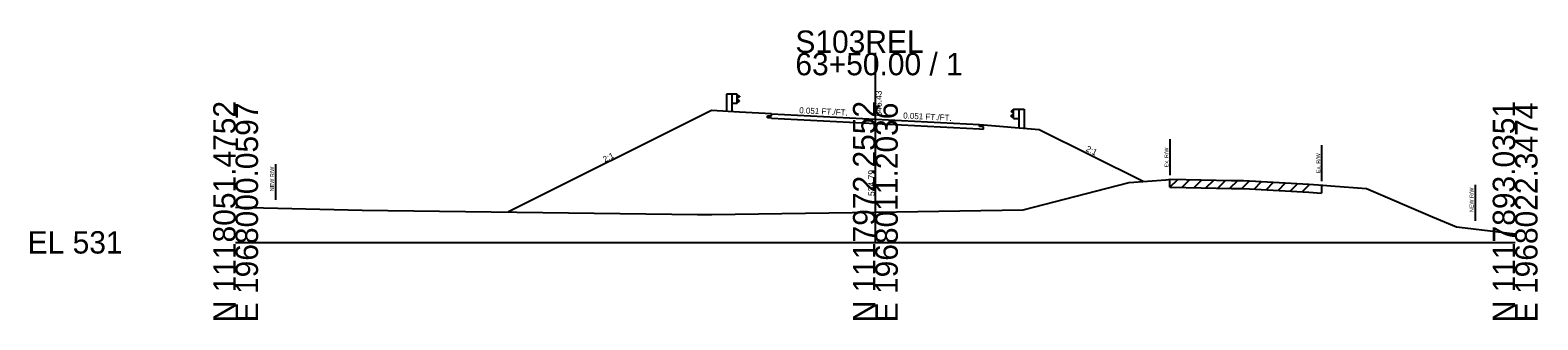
# Model space of a CAD drawing. Extents: x -26 to 163, y -10 to 45020.
# Drawn here: x -25.7 to 162.8, y 21490.3 to 21526.5 of the extents above; entities that cross this region are included whole.
import ezdxf

# ---------------------------------------------------------------- set-up
doc = ezdxf.new("R2010")
doc.units = 0
for name, color, linetype in [('RD_GPK_XS_Cell', 7, 'Continuous'), ('RD_XS_Base', 7, 'Continuous'), ('RD_XS_EarthShd', 7, 'Continuous'), ('RD_XS_ExGround', 7, 'Continuous'), ('RD_XS_ExPaveRet', 7, 'Continuous'), ('RD_XS_ExRW', 7, 'Continuous'), ('RD_XS_GR', 7, 'Continuous'), ('RD_XS_NewRW', 7, 'Continuous'), ('RD_XS_Pave', 7, 'Continuous'), ('RD_XS_PaveOvlay', 7, 'Continuous'), ('RD_XS_TieSlope', 7, 'Continuous'), ('RD_XS_TX_Elev_EX', 7, 'Continuous'), ('RD_XS_TX_Elev_PR', 7, 'Continuous'), ('RD_XS_TX_Slope', 7, 'Continuous')]:
    doc.layers.add(name, color=color, linetype=linetype)

msp = doc.modelspace()

# ---------------------------------------------------------------- linework, layer by layer
at = {"layer": 'RD_GPK_XS_Cell'}
for p, q in [((80, 21500), (80, 21523.7)), ((0, 21500), (80, 21500)), ((80, 21500), (160, 21500))]:
    msp.add_line(p, q, dxfattribs=at)
at = {"layer": 'RD_XS_Base'}
for p, q in [((67, 21515.53), (80, 21514.87)), ((80, 21514.87), (93, 21514.2))]:
    msp.add_line(p, q, dxfattribs=at)
at = {"layer": 'RD_XS_EarthShd'}
for p, q in [((63, 21516.3), (59.5, 21516.48)), ((67, 21516.09), (63, 21516.3)), ((93, 21514.76), (100.5, 21514.13))]:
    msp.add_line(p, q, dxfattribs=at)
at = {"layer": 'RD_XS_ExGround'}
for p, q in [((111.73, 21507.5), (116.33, 21507.84)), ((116.33, 21507.84), (116.96, 21507.9)), ((116.96, 21507.9), (124.54, 21507.75)), ((98.47, 21504.07), (110.26, 21507.11)), ((110.26, 21507.11), (111.73, 21507.5)), ((124.54, 21507.75), (126.03, 21507.74)), ((126.03, 21507.74), (134.19, 21507.26)), ((134.19, 21507.26), (135.94, 21507.17)), ((135.94, 21507.17), (136.95, 21507.08)), ((136.95, 21507.08), (141.41, 21506.75)), ((141.41, 21506.75), (149.67, 21503.2)), ((0, 21504.42), (15.81, 21504.04)), ((15.81, 21504.04), (57.75, 21503.49)), ((80, 21503.79), (98.47, 21504.07)), ((57.75, 21503.49), (58.36, 21503.48)), ((58.36, 21503.48), (59.54, 21503.49)), ((59.54, 21503.49), (80, 21503.79)), ((149.67, 21503.2), (152.68, 21501.96)), ((152.68, 21501.96), (153.77, 21501.83)), ((153.77, 21501.83), (160, 21501.08))]:
    msp.add_line(p, q, dxfattribs=at)
at = {"layer": 'RD_XS_ExPaveRet'}
for p, q in [((116.84, 21506.89), (116.84, 21507.89)), ((116.84, 21506.89), (117.83, 21507.88)), ((118.34, 21506.87), (119.32, 21507.85)), ((119.84, 21506.84), (120.82, 21507.82)), ((116.84, 21506.89), (116.96, 21506.9)), ((116.96, 21506.9), (124.54, 21506.75)), ((121.34, 21506.81), (122.32, 21507.8)), ((122.84, 21506.79), (123.82, 21507.77)), ((124.34, 21506.76), (125.33, 21507.75)), ((124.54, 21506.75), (126.03, 21506.74)), ((125.84, 21506.74), (126.8, 21507.7)), ((126.03, 21506.74), (134.19, 21506.26)), ((127.35, 21506.66), (128.29, 21507.61)), ((128.85, 21506.57), (129.79, 21507.52)), ((130.35, 21506.48), (131.29, 21507.43)), ((131.85, 21506.39), (132.79, 21507.34)), ((133.35, 21506.31), (134.3, 21507.25)), ((134.19, 21506.26), (135.8, 21506.17)), ((135.8, 21507.17), (135.8, 21506.17))]:
    msp.add_line(p, q, dxfattribs=at)
at = {"layer": 'RD_XS_ExRW'}
for p, q in [((116.84, 21512.89), (116.84, 21508.39)), ((135.8, 21512.17), (135.8, 21507.67))]:
    msp.add_line(p, q, dxfattribs=at)
at = {"layer": 'RD_XS_GR'}
for p, q in [((62.06, 21518.55), (61.4, 21518.55)), ((61.4, 21518.55), (61.4, 21516.38)), ((62.06, 21518.55), (61.4, 21518.55)), ((62.73, 21518.55), (62.06, 21518.55)), ((62.06, 21518.55), (62.06, 21516.35)), ((62.73, 21518.55), (62.06, 21518.55)), ((62.73, 21517.38), (62.06, 21517.38)), ((62.73, 21517.38), (62.06, 21517.38)), ((62.73, 21517.38), (62.73, 21518.55)), ((62.73, 21517.38), (62.73, 21518.55)), ((62.73, 21518.47), (63, 21518.27)), ((62.73, 21518.47), (63, 21518.27)), ((63, 21518.22), (62.73, 21518.02)), ((63, 21518.22), (62.73, 21518.02)), ((63, 21517.7), (62.73, 21517.9)), ((63, 21517.7), (62.73, 21517.9)), ((62.73, 21517.45), (63, 21517.65)), ((62.73, 21517.45), (63, 21517.65)), ((63, 21518.27), (63, 21518.22)), ((63, 21518.27), (63, 21518.22)), ((63, 21517.65), (63, 21517.7)), ((63, 21517.65), (63, 21517.7)), ((97.27, 21516.6), (97, 21516.4)), ((97, 21516.4), (97, 21516.35)), ((97, 21516.35), (97.27, 21516.15)), ((97, 21515.83), (97.27, 21516.03)), ((97, 21515.78), (97, 21515.83)), ((97.27, 21515.58), (97, 21515.78)), ((97.27, 21515.51), (97.27, 21516.67)), ((97.27, 21516.67), (97.94, 21516.67)), ((97.27, 21515.51), (97.94, 21515.51)), ((97.94, 21516.67), (97.94, 21514.35)), ((97.94, 21516.67), (98.6, 21516.67)), ((98.6, 21516.67), (98.6, 21514.29))]:
    msp.add_line(p, q, dxfattribs=at)
at = {"layer": 'RD_XS_NewRW'}
for p, q in [((5, 21509.8), (5, 21505.3)), ((155, 21507.18), (155, 21502.68))]:
    msp.add_line(p, q, dxfattribs=at)
at = {"layer": 'RD_XS_Pave'}
for p, q in [((66.5, 21515.84), (67, 21515.81)), ((66.5, 21515.56), (66.5, 21515.84)), ((67, 21515.53), (66.5, 21515.56)), ((67, 21515.81), (67, 21516.09)), ((93, 21514.48), (93, 21514.76)), ((93.5, 21514.45), (93, 21514.48)), ((93, 21514.2), (93.5, 21514.17)), ((93.5, 21514.17), (93.5, 21514.45))]:
    msp.add_line(p, q, dxfattribs=at)
at = {"layer": 'RD_XS_PaveOvlay'}
for p, q in [((67, 21516.09), (80, 21515.43)), ((80, 21515.43), (93, 21514.76))]:
    msp.add_line(p, q, dxfattribs=at)
at = {"layer": 'RD_XS_TieSlope'}
for p, q in [((59.5, 21516.48), (34.14, 21503.8)), ((100.5, 21514.13), (113.5, 21507.64))]:
    msp.add_line(p, q, dxfattribs=at)

# ---------------------------------------------------------------- texts
at = {"layer": 'RD_GPK_XS_Cell'}
for s, p in [('S103REL', (70, 21523.7)), ('63+50.00 / 1', (70, 21520.9)), ('EL 531', (-26, 21498.6))]:
    msp.add_text(s, height=2.8, dxfattribs=at).set_placement(p)
for s, p in [('N 1118051.4752', (0, 21490)), ('E 1968000.0597', (2.8, 21490)), ('N 1117972.2552', (80, 21490)), ('E 1968011.2036', (82.8, 21490)), ('N 1117893.0351', (160, 21490)), ('E 1968022.3474', (162.8, 21490))]:
    msp.add_text(s, height=2.8, rotation=90, dxfattribs=at).set_placement(p)
at = {"layer": 'RD_XS_ExRW'}
for p in [(116.65, 21509.39), (135.62, 21508.68)]:
    msp.add_text('Ex. R/W ', height=0.488, rotation=90, dxfattribs=at).set_placement(p)
at = {"layer": 'RD_XS_NewRW'}
for p in [(4.8, 21506.4), (154.8, 21503.79)]:
    msp.add_text('NEW R/W ', height=0.488, rotation=90, dxfattribs=at).set_placement(p)
at = {"layer": 'RD_XS_TX_Elev_EX'}
msp.add_text('534.79', height=0.8, rotation=90, dxfattribs=at).set_placement((79.9, 21505.79))
at = {"layer": 'RD_XS_TX_Elev_PR'}
msp.add_text(' 546.43', height=0.8, rotation=90, dxfattribs=at).set_placement((80.8, 21515.43))
at = {"layer": 'RD_XS_TX_Slope'}
for s, rotation, p in [('0.051 FT./FT.', 357.0633, (70.46, 21516.16)), ('0.051 FT./FT.', 357.0633, (83.46, 21515.5)), ('2:1', 333.4349, (106.25, 21511.46)), ('2:1', 26.5651, (46.16, 21509.99))]:
    msp.add_text(s, height=0.75, rotation=rotation, dxfattribs=at).set_placement(p)

doc.saveas('drawing.dxf')
